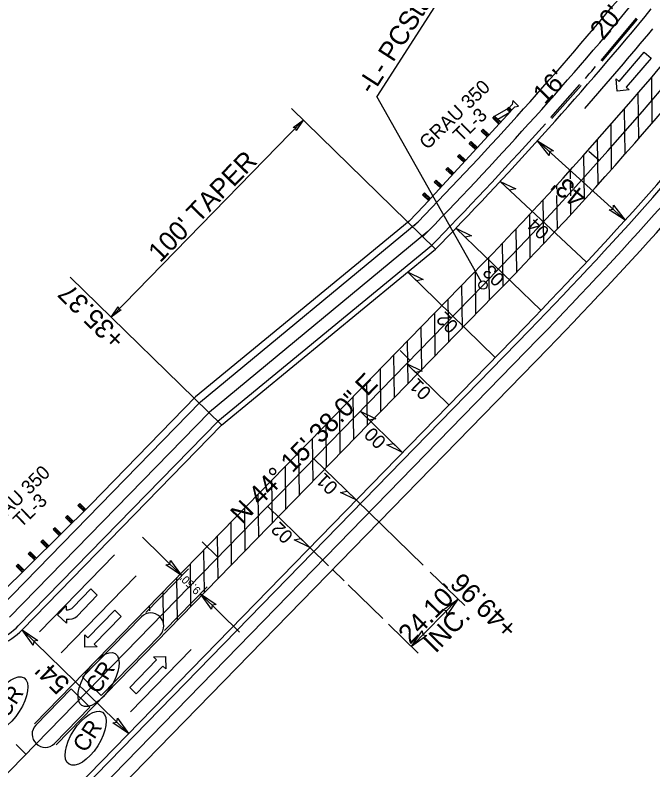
# Model space of a CAD drawing. Extents: x 1974386 to 1979988, y 776712 to 784860.
# Drawn here: x 1976819.6 to 1977051.5, y 779962.3 to 780236.8 of the extents above; entities that cross this region are included whole.
import ezdxf

# ---------------------------------------------------------------- set-up
doc = ezdxf.new("R2010")
doc.units = 0
for name, color, linetype in [('Prop Conc 2ft 6in Curb and Gutter', 7, 'Continuous'), ('Prop Conc 4in Sidewalk', 7, 'Continuous'), ('Prop Conc 5in Monolithic Keyed In Island', 7, 'Continuous'), ('Prop Conc Drive Drop Type', 7, 'Continuous'), ('Prop Conc Drive Radius Type', 7, 'Continuous'), ('Prop Dimension', 7, 'Continuous'), ('Prop Dimension Text', 7, 'Continuous'), ('Prop EOT', 7, 'Continuous'), ('Prop Guardrail', 7, 'Continuous'), ('Prop Guardrail Anchor Unit CELL', 7, 'Continuous'), ('Prop Horizontal Alignment', 7, 'Continuous'), ('Prop Horizontal Alignment Direction Label', 7, 'Continuous'), ('Prop Horizontal Alignment Station Label', 7, 'Continuous'), ('Prop Horizontal Alignment Tick Large', 7, 'Continuous'), ('Prop Horizontal Alignment Tick Small', 7, 'Continuous'), ('Prop Lane Arrow CELL', 7, 'Continuous'), ('Prop Lane Lines', 7, 'Continuous'), ('Prop Superelevation  Arrow CELL', 7, 'Continuous'), ('Prop Superelevation Label', 7, 'Continuous'), ('Prop Terminator CELL', 7, 'Continuous'), ('Prop WCC CELL', 7, 'Continuous')]:
    doc.layers.add(name, color=color, linetype=linetype)

msp = doc.modelspace()

# ---------------------------------------------------------------- linework, layer by layer
at = {"layer": 'Prop Conc 2ft 6in Curb and Gutter'}
for p, q in [((1976893.3, 780089.08), (1976971, 780153.04)), ((1976971, 780153.04), (1976972.91, 780155)), ((1976688.32, 779795.62), (1977006.57, 780122.2)), ((1976820.76, 780014.63), (1976893.39, 780089.16))]:
    msp.add_line(p, q, dxfattribs=at)
for centre, radius, start, end in [((1975987.1, 781115.69), 1423.5, 315.73946, 321.40587), ((1975987.1, 781115.69), 1376.5, 319.06379, 319.29879), ((1975987.1, 781115.69), 1376.5, 315.73946, 318.14799), ((1976804.29, 780030.68), 23, 224.3953, 315.7395)]:
    msp.add_arc(centre, radius, start, end, dxfattribs=at)
at = {"layer": 'Prop Conc 4in Sidewalk'}
for p, q in [((1976886.99, 780096.2), (1976966.11, 780161.63)), ((1976964.64, 780160.12), (1976966.11, 780161.63)), ((1976969.69, 780158.14), (1976890.27, 780092.42)), ((1976968.01, 780156.42), (1976969.69, 780158.14)), ((1976586.27, 779684.45), (1977009.79, 780119.06)), ((1977009.79, 780119.06), (1976586.27, 779684.45)), ((1976589.85, 779680.96), (1977013.37, 780115.57)), ((1976589.85, 779680.96), (1977013.37, 780115.57)), ((1976813.97, 780021.28), (1976886.99, 780096.2)), ((1976890.27, 780092.42), (1976817.55, 780017.79))]:
    msp.add_line(p, q, dxfattribs=at)
for radius, end in [(1367, 320.45193), (1372, 320.5086), (1428, 321.41478), (1428, 321.41478), (1433, 321.41478), (1433, 321.41478)]:
    msp.add_arc((1975987.1, 781115.69), radius, 315.73946, end, dxfattribs=at)
at = {"layer": 'Prop Conc 5in Monolithic Keyed In Island'}
for p, q in [((1976844.15, 779996.01), (1976865.52, 780017.94)), ((1976872.33, 780011.31), (1976850.95, 779989.38)), ((1976850.95, 779989.38), (1976844.15, 779996.01)), ((1976827.14, 779978.55), (1976839.96, 779991.71)), ((1976839.96, 779991.71), (1976846.76, 779985.08)), ((1976846.76, 779985.08), (1976833.94, 779971.92))]:
    msp.add_line(p, q, dxfattribs=at)
for centre, start, end in [((1976868.93, 780014.62), 315.7395, 135.7395), ((1976830.54, 779975.23), 135.7395, 315.7394)]:
    msp.add_arc(centre, 4.75, start, end, dxfattribs=at)
at = {"layer": 'Prop Conc Drive Drop Type'}
for p, q in [((1977033.03, 780220), (1977045.89, 780235.33)), ((1977014.78, 780199.18), (1977025.36, 780211.19))]:
    msp.add_line(p, q, dxfattribs=at)
at = {"layer": 'Prop Conc Drive Radius Type'}
for p, q in [((1977032.65, 780220.33), (1977045.51, 780235.65)), ((1977014.41, 780199.51), (1977024.98, 780211.52))]:
    msp.add_line(p, q, dxfattribs=at)
at = {"layer": 'Prop Dimension'}
for p, q in [((1976920.15, 780202.79), (1976972.43, 780151.65)), ((1976924.39, 780198.61), (1976854.52, 780126.92)), ((1976839.62, 780141.44), (1976894.77, 780087.7)), ((1976967.95, 780036.75), (1976943.62, 780060.47)), ((1976880.16, 780032.96), (1976865.88, 780046.88)), ((1976933.56, 780036.56), (1976926.77, 780043.18)), ((1976867.13, 780019.59), (1976882.6, 780035.47)), ((1976939.19, 780031.08), (1976934.92, 780035.24)), ((1976983.06, 780022.03), (1976970.53, 780034.24)), ((1976873.93, 780012.96), (1976889.41, 780028.84)), ((1976953.3, 780017.32), (1976940.67, 780029.63)), ((1976901.25, 780012.41), (1976886.96, 780026.33)), ((1976980.6, 780024.43), (1976963.75, 780007.14)), ((1976966.21, 780004.74), (1976955.4, 780015.28)), ((1976860.88, 779975.56), (1976822.21, 780013.25))]:
    msp.add_line(p, q, dxfattribs=at)
at = {"layer": 'Prop Dimension Text'}
msp.add_line((1977041.44, 780162.26), (1977009.55, 780191.1), dxfattribs=at)
at = {"layer": 'Prop EOT'}
for p, q in [((1976972.44, 780151.65), (1976974.34, 780153.6)), ((1976894.7, 780087.64), (1976972.44, 780151.65)), ((1976581.61, 779688.99), (1977005.14, 780123.59)), ((1976822.21, 780013.25), (1976894.7, 780087.64))]:
    msp.add_line(p, q, dxfattribs=at)
for centre, radius, start, end in [((1975987.1, 781115.69), 1378.5, 315.73946, 320.5086), ((1975987.1, 781115.69), 1421.5, 315.73946, 321.40587), ((1976804.29, 780030.68), 25, 224.3953, 315.7395)]:
    msp.add_arc(centre, radius, start, end, dxfattribs=at)
at = {"layer": 'Prop Guardrail'}
for p, q in [((1976968.22, 780167.48), (1976962.87, 780161.89)), ((1976962.87, 780161.89), (1976885.2, 780097.95)), ((1976885.2, 780097.95), (1976847.08, 780058.84))]:
    msp.add_line(p, q, dxfattribs=at)
at = {"layer": 'Prop Guardrail Anchor Unit CELL'}
for p, q in [((1977000.55, 780205.74), (1977000.36, 780204.29)), ((1977002.68, 780203.71), (1977000.55, 780205.74)), ((1976968.22, 780167.48), (1976999.86, 780201.9)), ((1976993.95, 780199.99), (1976998.42, 780202.54)), ((1976998.42, 780202.54), (1976999.1, 780203.28)), ((1976998.42, 780202.54), (1976998.76, 780202.91)), ((1976999.53, 780201.53), (1976998.42, 780202.54)), ((1977000.2, 780202.26), (1976998.42, 780202.54)), ((1977000.36, 780204.29), (1976998.94, 780202.81)), ((1976998.94, 780202.81), (1976999.39, 780202.39)), ((1977000.2, 780202.26), (1976999.1, 780203.28)), ((1976999.1, 780203.28), (1976999.53, 780201.53)), ((1976999.39, 780202.39), (1976999.83, 780201.97)), ((1976999.83, 780201.97), (1977001.24, 780203.45)), ((1977001.24, 780203.45), (1977002.68, 780203.71)), ((1976993.28, 780199.26), (1976993.95, 780199.99)), ((1976995.53, 780197.18), (1976993.28, 780199.26)), ((1976995.08, 780198.96), (1976993.28, 780199.26)), ((1976996.21, 780197.92), (1976993.95, 780199.99)), ((1976993.95, 780199.99), (1976994.4, 780198.22)), ((1976994.4, 780198.22), (1976995.08, 780198.96)), ((1976995.08, 780198.96), (1976999.53, 780201.53)), ((1976995.53, 780197.18), (1976995.08, 780198.96)), ((1976994.4, 780198.22), (1976996.21, 780197.92)), ((1976989.06, 780194.58), (1976989.73, 780195.31)), ((1976991.27, 780192.55), (1976989.06, 780194.58)), ((1976990.84, 780194.3), (1976989.06, 780194.58)), ((1976991.94, 780193.28), (1976989.73, 780195.31)), ((1976989.73, 780195.31), (1976990.16, 780193.56)), ((1976990.16, 780193.56), (1976990.84, 780194.3)), ((1976990.16, 780193.56), (1976991.94, 780193.28)), ((1976991.27, 780192.55), (1976990.84, 780194.3)), ((1976984.69, 780190.03), (1976985.37, 780190.77)), ((1976987.68, 780188.64), (1976985.37, 780190.77)), ((1976985.37, 780190.77), (1976985.85, 780188.97)), ((1976987, 780187.91), (1976984.69, 780190.03)), ((1976986.52, 780189.7), (1976984.69, 780190.03)), ((1976985.85, 780188.97), (1976986.52, 780189.7)), ((1976985.85, 780188.97), (1976987.68, 780188.64)), ((1976987, 780187.91), (1976986.52, 780189.7)), ((1976980.5, 780185.32), (1976981.18, 780186.06)), ((1976982.74, 780183.27), (1976980.5, 780185.32)), ((1976982.3, 780185.03), (1976980.5, 780185.32)), ((1976983.41, 780184.01), (1976981.18, 780186.06)), ((1976981.18, 780186.06), (1976981.62, 780184.3)), ((1976981.62, 780184.3), (1976982.3, 780185.03)), ((1976981.62, 780184.3), (1976983.41, 780184.01)), ((1976982.74, 780183.27), (1976982.3, 780185.03)), ((1976982.74, 780183.27), (1976983.41, 780184.01)), ((1976976.23, 780180.69), (1976976.9, 780181.43)), ((1976978.47, 780178.63), (1976976.23, 780180.69)), ((1976978.03, 780180.4), (1976976.23, 780180.69)), ((1976979.15, 780179.37), (1976976.9, 780181.43)), ((1976976.9, 780181.43), (1976977.35, 780179.66)), ((1976977.35, 780179.66), (1976978.03, 780180.4)), ((1976978.47, 780178.63), (1976978.03, 780180.4)), ((1976977.35, 780179.66), (1976979.15, 780179.37)), ((1976971.96, 780176.06), (1976972.64, 780176.79)), ((1976974.21, 780173.99), (1976971.96, 780176.06)), ((1976973.76, 780175.76), (1976971.96, 780176.06)), ((1976974.88, 780174.73), (1976972.64, 780176.79)), ((1976972.64, 780176.79), (1976973.08, 780175.03)), ((1976973.08, 780175.03), (1976973.76, 780175.76)), ((1976973.08, 780175.03), (1976974.88, 780174.73)), ((1976974.21, 780173.99), (1976973.76, 780175.76)), ((1976967.73, 780171.38), (1976968.41, 780172.12)), ((1976970.62, 780170.09), (1976968.41, 780172.12)), ((1976968.41, 780172.12), (1976968.84, 780170.37)), ((1976969.94, 780169.35), (1976967.73, 780171.38)), ((1976969.51, 780171.11), (1976967.73, 780171.38)), ((1976968.84, 780170.37), (1976969.51, 780171.11)), ((1976968.84, 780170.37), (1976970.62, 780170.09)), ((1976970.62, 780170.09), (1976969.51, 780171.11)), ((1976969.51, 780171.11), (1976969.94, 780169.35)), ((1976969.94, 780169.35), (1976970.62, 780170.09)), ((1976843.17, 780059.19), (1976842.45, 780058.49)), ((1976845.27, 780057.05), (1976843.17, 780059.19)), ((1976843.51, 780057.42), (1976843.17, 780059.19)), ((1976847.08, 780058.84), (1976813.79, 780026.01)), ((1976844.56, 780056.35), (1976842.45, 780058.49)), ((1976842.45, 780058.49), (1976844.22, 780058.12)), ((1976844.22, 780058.12), (1976843.51, 780057.42)), ((1976844.56, 780056.35), (1976843.51, 780057.42)), ((1976843.51, 780057.42), (1976845.27, 780057.05)), ((1976844.22, 780058.12), (1976844.56, 780056.35)), ((1976845.27, 780057.05), (1976844.56, 780056.35)), ((1976838.64, 780054.8), (1976837.93, 780054.1)), ((1976840.07, 780051.93), (1976837.93, 780054.1)), ((1976837.93, 780054.1), (1976839.71, 780053.71)), ((1976840.79, 780052.63), (1976838.64, 780054.8)), ((1976839, 780053.01), (1976838.64, 780054.8)), ((1976839.71, 780053.71), (1976839, 780053.01)), ((1976839.71, 780053.71), (1976840.07, 780051.93)), ((1976840.79, 780052.63), (1976839, 780053.01)), ((1976834.16, 780050.37), (1976833.45, 780049.67)), ((1976835.59, 780047.5), (1976833.45, 780049.67)), ((1976833.45, 780049.67), (1976835.23, 780049.29)), ((1976836.3, 780048.2), (1976834.16, 780050.37)), ((1976834.52, 780048.59), (1976834.16, 780050.37)), ((1976835.23, 780049.29), (1976834.52, 780048.59)), ((1976836.3, 780048.2), (1976834.52, 780048.59)), ((1976835.23, 780049.29), (1976835.59, 780047.5)), ((1976829.68, 780045.94), (1976828.97, 780045.24)), ((1976831.1, 780043.08), (1976828.97, 780045.24)), ((1976828.97, 780045.24), (1976830.75, 780044.86)), ((1976831.81, 780043.78), (1976829.68, 780045.94)), ((1976830.03, 780044.16), (1976829.68, 780045.94)), ((1976830.75, 780044.86), (1976830.03, 780044.16)), ((1976831.81, 780043.78), (1976830.03, 780044.16)), ((1976830.75, 780044.86), (1976831.1, 780043.08)), ((1976831.81, 780043.78), (1976831.1, 780043.08)), ((1976825.12, 780041.59), (1976824.41, 780040.89)), ((1976826.61, 780038.65), (1976824.41, 780040.89)), ((1976824.41, 780040.89), (1976826.22, 780040.47)), ((1976827.32, 780039.36), (1976825.12, 780041.59)), ((1976825.51, 780039.77), (1976825.12, 780041.59)), ((1976826.22, 780040.47), (1976825.51, 780039.77)), ((1976827.32, 780039.36), (1976825.51, 780039.77)), ((1976826.22, 780040.47), (1976826.61, 780038.65)), ((1976820.73, 780037.07), (1976820.02, 780036.37)), ((1976822.84, 780034.93), (1976820.73, 780037.07)), ((1976821.07, 780035.3), (1976820.73, 780037.07)), ((1976822.12, 780034.23), (1976820.02, 780036.37)), ((1976820.02, 780036.37), (1976821.78, 780036)), ((1976821.78, 780036), (1976821.07, 780035.3)), ((1976822.84, 780034.93), (1976821.07, 780035.3)), ((1976821.78, 780036), (1976822.12, 780034.23))]:
    msp.add_line(p, q, dxfattribs=at)
at = {"layer": 'Prop Horizontal Alignment'}
msp.add_line((1976566.21, 779704), (1976989.74, 780138.6), dxfattribs=at)
msp.add_arc((1975987.1, 781115.69), 1400, 315.73946, 340.62647, dxfattribs=at)
at = {"layer": 'Prop Horizontal Alignment Station Label'}
for p in [(1977001.66, 780285.97), (1976989, 780139.9)]:
    msp.add_line(p, (1976951.08, 780207.22), dxfattribs=at)
msp.add_circle((1976989.74, 780138.6), 1.5, dxfattribs=at)
at = {"layer": 'Prop Horizontal Alignment Tick Large'}
msp.add_line((1976893.35, 780039.69), (1976887.62, 780045.27), dxfattribs=at)
at = {"layer": 'Prop Horizontal Alignment Tick Small'}
for p, q in [((1977031.94, 780183.87), (1977028.21, 780187.19)), ((1976963.15, 780111.31), (1976959.56, 780114.8)), ((1976823.56, 779968.07), (1976819.98, 779971.56))]:
    msp.add_line(p, q, dxfattribs=at)
at = {"layer": 'Prop Lane Arrow CELL'}
for p, q in [((1977039.27, 780212.68), (1977048.38, 780223.32)), ((1977050.88, 780221.17), (1977041.78, 780210.54)), ((1977048.38, 780223.32), (1977050.88, 780221.17)), ((1977038.52, 780209.19), (1977038.13, 780213.66)), ((1977038.13, 780213.66), (1977039.27, 780212.68)), ((1977041.78, 780210.54), (1977042.92, 780209.56)), ((1977042.92, 780209.56), (1977038.52, 780209.19)), ((1976840.75, 780021.49), (1976847.09, 780028.08)), ((1976847.09, 780028.08), (1976849.47, 780025.8)), ((1976849.47, 780025.8), (1976842.16, 780018.19)), ((1976835.07, 780018.69), (1976838.16, 780021.97)), ((1976838.16, 780021.97), (1976838.19, 780020.48)), ((1976838.28, 780015.68), (1976835.07, 780018.69)), ((1976845.99, 780010.35), (1976855.81, 780020.34)), ((1976858.16, 780018.02), (1976848.35, 780008.04)), ((1976855.81, 780020.34), (1976858.16, 780018.02)), ((1976838.25, 780017.16), (1976838.28, 780015.68)), ((1976845, 780006.91), (1976844.92, 780011.4)), ((1976844.92, 780011.4), (1976845.99, 780010.35)), ((1976849.42, 780006.99), (1976845, 780006.91)), ((1976848.35, 780008.04), (1976849.42, 780006.99)), ((1976861.27, 779992.26), (1976870.98, 780002.34)), ((1976869.9, 780003.38), (1976874.32, 780003.5)), ((1976870.98, 780002.34), (1976869.9, 780003.38)), ((1976874.32, 780003.5), (1976874.44, 779999.01)), ((1976873.36, 780000.05), (1976863.64, 779989.97)), ((1976874.44, 779999.01), (1976873.36, 780000.05)), ((1976863.64, 779989.97), (1976861.27, 779992.26))]:
    msp.add_line(p, q, dxfattribs=at)
for centre, radius, start, end in [((1976838.39, 780023.74), 3.27, 266.4582, 316.1164), ((1976838.97, 780022.35), 5.25, 262.1286, 307.4403)]:
    msp.add_arc(centre, radius, start, end, dxfattribs=at)
at = {"layer": 'Prop Lane Lines'}
for p, q in [((1977051.27, 780197.56), (1977051.06, 780214.24)), ((1977046.35, 780191.88), (1977046.13, 780208.46)), ((1977041.42, 780186.26), (1977041.21, 780202.74)), ((1977036.49, 780180.7), (1977036.28, 780197.08)), ((1977031.56, 780175.2), (1977031.35, 780191.48)), ((1977026.63, 780169.75), (1977026.42, 780185.94)), ((1977021.54, 780177.19), (1977021.49, 780180.46)), ((1977016.58, 780173.54), (1977016.56, 780175.03)), ((1977021.61, 780171.12), (1977021.55, 780175.81)), ((1977011.84, 780153.74), (1977011.63, 780169.67)), ((1977016.77, 780159.03), (1977016.61, 780171.22)), ((1977021.7, 780164.36), (1977021.64, 780168.82)), ((1977006.9, 780148.52), (1977006.7, 780164.35)), ((1977001.97, 780143.34), (1977001.77, 780159.09)), ((1976997.04, 780138.22), (1976996.83, 780153.89)), ((1976992.1, 780133.14), (1976991.9, 780148.73)), ((1976826.6, 779979.07), (1976985.8, 780142.44)), ((1976987.17, 780128.08), (1976986.97, 780143.63)), ((1976982.23, 780123.01), (1976982.03, 780138.57)), ((1976834.48, 779971.4), (1976993.68, 780134.76)), ((1976977.3, 780117.95), (1976977.1, 780133.5)), ((1976972.36, 780112.88), (1976972.16, 780128.44)), ((1976967.43, 780107.82), (1976967.23, 780123.37)), ((1976962.49, 780102.76), (1976962.29, 780118.31)), ((1976957.56, 780097.69), (1976957.36, 780113.25)), ((1976952.62, 780092.63), (1976952.42, 780108.18)), ((1976947.69, 780087.56), (1976947.48, 780103.12)), ((1976942.75, 780082.5), (1976942.55, 780098.05)), ((1976937.82, 780077.44), (1976937.61, 780092.99)), ((1976932.88, 780072.37), (1976932.68, 780087.93)), ((1976927.95, 780067.31), (1976927.74, 780082.86)), ((1976923.01, 780062.24), (1976922.81, 780077.8)), ((1976918.08, 780057.18), (1976917.87, 780072.73)), ((1976913.14, 780052.11), (1976912.94, 780067.67)), ((1976908.21, 780047.05), (1976908, 780062.61)), ((1976903.27, 780041.99), (1976903.07, 780057.54)), ((1976898.34, 780036.92), (1976898.13, 780052.48)), ((1976893.4, 780031.86), (1976893.2, 780047.41)), ((1976828.44, 780012.49), (1976855.75, 780040.5)), ((1976888.47, 780026.79), (1976888.26, 780042.35)), ((1976883.53, 780021.73), (1976883.33, 780037.29)), ((1976836.32, 780004.81), (1976863.63, 780032.83)), ((1976878.59, 780016.67), (1976878.39, 780032.22)), ((1976873.61, 780015.41), (1976873.46, 780027.16)), ((1976868.55, 780020.11), (1976868.52, 780022.09)), ((1976873.66, 780011.6), (1976873.66, 780011.82)), ((1976861.58, 779983.44), (1976883.65, 780006.09))]:
    msp.add_line(p, q, dxfattribs=at)
for radius, start, end in [(1394.5, 315.73946, 322.77439), (1405.5, 315.73946, 322.77439), (1383.5, 318.71501, 320.29496)]:
    msp.add_arc((1975987.1, 781115.69), radius, start, end, dxfattribs=at)
at = {"layer": 'Prop Superelevation  Arrow CELL'}
for p, q in [((1977027.41, 780146.97), (1976995.94, 780176.28)), ((1977010.81, 780129.45), (1976979.85, 780159.28)), ((1976962.25, 780143.43), (1976994.16, 780112.33)), ((1976961.92, 780110.05), (1976977.31, 780095.04)), ((1976945.07, 780092.76), (1976960.47, 780077.75)), ((1976928.22, 780075.47), (1976943.62, 780060.47)), ((1976911.37, 780058.18), (1976926.77, 780043.18))]:
    msp.add_line(p, q, dxfattribs=at)
for points in [[(1976995.94, 780176.28), (1977001.7, 780173.65), (1976999.33, 780173.13)], [(1976979.85, 780159.28), (1976985.56, 780156.56), (1976983.18, 780156.08)], [(1976962.25, 780143.43), (1976967.94, 780140.67), (1976965.56, 780140.2)], [(1976961.92, 780110.05), (1976967.61, 780107.29), (1976965.23, 780106.82)], [(1976945.07, 780092.76), (1976950.76, 780090), (1976948.38, 780089.53)], [(1976960.47, 780077.75), (1976954.77, 780080.51), (1976957.15, 780080.98)], [(1976943.62, 780060.47), (1976937.93, 780063.22), (1976940.31, 780063.69)], [(1976926.77, 780043.18), (1976921.08, 780045.93), (1976923.46, 780046.4)]]:
    msp.add_lwpolyline(points, close=True, dxfattribs=at)
at = {"layer": 'Prop Terminator CELL'}
for points in [[(1976920.69, 780195.93), (1976924.39, 780198.61), (1976921.8, 780194.81), (1976921.63, 780195.78)], [(1977013.77, 780185.71), (1977009.55, 780191.1), (1977015.39, 780187.44), (1977013.94, 780187.13)], [(1977037.21, 780167.65), (1977041.44, 780162.26), (1977035.6, 780165.93), (1977037.05, 780166.24)], [(1976858.22, 780129.6), (1976854.52, 780126.92), (1976857.11, 780130.72), (1976857.28, 780129.75)], [(1976876.14, 780038.5), (1976880.16, 780032.96), (1976874.46, 780036.84), (1976875.92, 780037.09)], [(1976890.99, 780020.79), (1976886.96, 780026.33), (1976892.66, 780022.45), (1976891.21, 780022.19)], [(1976975.06, 780020.4), (1976980.6, 780024.43), (1976976.72, 780018.73), (1976976.46, 780020.18)], [(1976826.23, 780007.71), (1976822.21, 780013.25), (1976827.91, 780009.37), (1976826.45, 780009.12)], [(1976969.3, 780011.16), (1976963.75, 780007.14), (1976967.63, 780012.84), (1976967.89, 780011.38)], [(1976856.86, 779981.11), (1976860.88, 779975.56), (1976855.18, 779979.44), (1976856.64, 779979.7)]]:
    msp.add_lwpolyline(points, close=True, dxfattribs=at)
at = {"layer": 'Prop WCC CELL'}
for centre in [(1976849.95, 779995.13), (1976816.78, 779986.3), (1976845.27, 779973.8)]:
    msp.add_ellipse(centre, major_axis=(6.07, 9.43), ratio=0.462467, dxfattribs=at)

# ---------------------------------------------------------------- texts
at = {"layer": 'Prop Dimension'}
for s, height, p in [('+35.37', 7, (1976860.21, 780119.6)), ("9.50'", 2.953, (1976887.38, 780027.83))]:
    msp.add_text(s, height=height, rotation=135.7395, dxfattribs=at).set_placement(p)
at = {"layer": 'Prop Dimension Text'}
for s, rotation, p in [("20'", 50.76, (1977033.42, 780227.33)), ("16'", 45.8189, (1977012.19, 780204.01)), ("100' TAPER", 45.8189, (1976872.35, 780146.52)), ("43'", 141.7216, (1977027.85, 780171.64)), ('+49.96', 135.8189, (1977002.85, 780014.34)), ("24.10'", 45.7395, (1976963.25, 780007.68)), ('INC.', 45.7395, (1976972.49, 780004.45)), ("54'", 135.361, (1976839.98, 779994.13))]:
    msp.add_text(s, height=7, rotation=rotation, dxfattribs=at).set_placement(p)
at = {"layer": 'Prop Guardrail Anchor Unit CELL'}
for s, p in [('GRAU 350', (1976969.49, 780187.6)), ('TL-3', (1976981.75, 780190.36)), ('GRAU 350', (1976809.52, 780047.39)), ('TL-3', (1976821.79, 780050.15))]:
    msp.add_text(s, height=5, rotation=44.1159, dxfattribs=at).set_placement(p)
at = {"layer": 'Prop Horizontal Alignment Direction Label'}
msp.add_text('N 44%%d 15\' 38.0" E', height=7, rotation=45.7395, dxfattribs=at).set_placement((1976902.21, 780051.34))
at = {"layer": 'Prop Horizontal Alignment Station Label'}
msp.add_text('-L- PCSta. 31+38.10', height=7, rotation=57.2884, dxfattribs=at).set_placement((1976949.44, 780207.58))
at = {"layer": 'Prop Superelevation Label'}
for s, rotation, p in [('04', 137.0411, (1977014.23, 780158.42)), ('03', 136.0683, (1976997.95, 780141.24)), ('02', 135.7395, (1976981.13, 780124.14)), ('01', 135.7395, (1976971.3, 780099.93)), ('00', 135.7395, (1976954.88, 780082.13)), ('01', 135.7395, (1976937.37, 780065.49)), ('02', 135.7395, (1976921.05, 780047.69))]:
    msp.add_text(s, height=5, rotation=rotation, dxfattribs=at).set_placement(p)
at = {"layer": 'Prop WCC CELL'}
for p in [(1976849.88, 779989.56), (1976816.72, 779980.73), (1976845.21, 779968.24)]:
    msp.add_text('CR', height=6, rotation=57.255, dxfattribs=at).set_placement(p)

doc.saveas('drawing.dxf')
